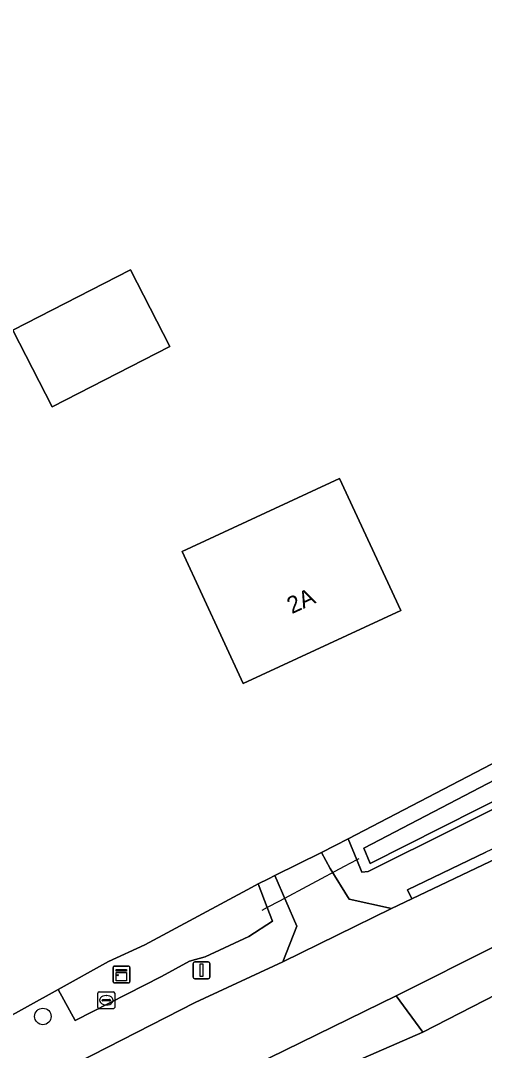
# Model space of a CAD drawing. Extents: x 164494 to 166241, y 382475 to 384495.
# Drawn here: x 165073.2 to 165100.7, y 383021.1 to 383082.2 of the extents above; entities that cross this region are included whole.
import ezdxf

# ---------------------------------------------------------------- set-up
doc = ezdxf.new("R2010")
doc.units = 0
for name, color, linetype in [('IMGEO_Berm_halfverhard', 7, 'Continuous'), ('IMGEO_Boom', 7, 'Continuous'), ('IMGEO_Duiker', 7, 'Continuous'), ('IMGEO_Erf', 7, 'Continuous'), ('IMGEO_Groenvoorziening', 7, 'Continuous'), ('IMGEO_Kast', 7, 'Continuous'), ('IMGEO_Lichtmast', 7, 'Continuous'), ('IMGEO_Oever', 7, 'Continuous'), ('IMGEO_Pand', 7, 'Continuous'), ('IMGEO_Pand_nummerreeks', 7, 'Continuous'), ('IMGEO_Rijbaan_lokaal_gesloten', 7, 'Continuous'), ('IMGEO_Rijbaan_lokaal_open', 7, 'Continuous'), ('IMGEO_Rioolput', 7, 'Continuous'), ('IMGEO_Waterloop', 7, 'Continuous')]:
    doc.layers.add(name, color=color, linetype=linetype)

msp = doc.modelspace()

# ---------------------------------------------------------------- linework, layer by layer
at = {"layer": 'IMGEO_Berm_halfverhard'}
msp.add_lwpolyline([(165124.917, 383044.186), (165114.926, 383039.545), (165106.055, 383035.28), (165100.825, 383032.871), (165096.175, 383030.648), (165096.433, 383030.107), (165101.084, 383032.33), (165106.315, 383034.739), (165115.179, 383039.001)], dxfattribs=at)
at = {"layer": 'IMGEO_Boom'}
msp.add_circle((165074.517, 383023.125), 0.489, dxfattribs=at)
at = {"layer": 'IMGEO_Duiker'}
msp.add_lwpolyline([(165093.282, 383032.484), (165093.164, 383032.421), (165092.411, 383032.019), (165088.575, 383029.973), (165087.842, 383029.582), (165087.517, 383029.409)], dxfattribs=at)
at = {"layer": 'IMGEO_Erf'}
for points in [[(165070.298, 383021.899), (165075.419, 383024.723), (165078.42, 383026.378), (165080.567, 383027.366), (165086.908, 383030.775), (165087.302, 383030.987), (165087.92, 383031.295), (165088.293, 383031.481), (165091.062, 383032.863), (165091.867, 383033.265), (165092.654, 383033.657), (165109.176, 383042.267), (165126.099, 383051.085), (165129.346, 383052.646), (165106.891, 383080.948), (165095.917, 383095.847), (165095.148, 383097.711), (165091.308, 383102.836), (165060.973, 383084.346)], [(165149.084, 382949.174), (165148.158, 382951.679), (165147.327, 382953.204), (165144.143, 382962.9), (165139.197, 382976.046), (165137.999, 382979.812), (165137.425, 382980.815), (165123.051, 383020.688), (165118.823, 383033.37), (165102.205, 383024.82), (165097.081, 383022.184), (165092.763, 383020.321), (165071.589, 383009.606), (165052.261, 382999.034), (165049.332, 382997.432), (165046.565, 382995.873), (165042.211, 382989.793), (165038.852, 382985.102), (165066.603, 382948.671), (165135.814, 382857.34)]]:
    msp.add_lwpolyline(points, dxfattribs=at)
for points in [[(165075.058, 383059.299), (165072.724, 383063.863), (165079.723, 383067.443), (165082.057, 383062.879)], [(165086.419, 383042.886), (165082.794, 383050.728), (165092.141, 383055.049), (165095.767, 383047.208)]]:
    msp.add_lwpolyline(points, close=True, dxfattribs=at)
at = {"layer": 'IMGEO_Groenvoorziening'}
msp.add_lwpolyline([(165130.436, 383049.949), (165093.844, 383031.73), (165093.464, 383031.692), (165093.164, 383032.421), (165092.654, 383033.657), (165091.867, 383033.265), (165091.062, 383032.863), (165091.582, 383031.909), (165092.716, 383030.076), (165095.219, 383029.526), (165096.433, 383030.107), (165096.175, 383030.648), (165100.825, 383032.871)], dxfattribs=at)
for points in [[(165088.775, 383026.373), (165089.6, 383028.476), (165088.293, 383031.481), (165087.92, 383031.295), (165087.302, 383030.987), (165087.842, 383029.582), (165088.149, 383028.783), (165086.745, 383027.872), (165084.158, 383026.667), (165083.217, 383026.412), (165081.553, 383025.502), (165076.433, 383022.884), (165075.419, 383024.723), (165070.298, 383021.899), (165072.217, 383018.147), (165083.565, 383023.951)], [(165088.149, 383028.783), (165087.842, 383029.582), (165087.302, 383030.987), (165086.908, 383030.775), (165080.567, 383027.366), (165078.42, 383026.378), (165075.419, 383024.723), (165076.433, 383022.884), (165081.553, 383025.502), (165083.217, 383026.412), (165084.158, 383026.667), (165086.745, 383027.872)], [(165092.763, 383020.321), (165097.081, 383022.184), (165095.49, 383024.344), (165083.246, 383018.36), (165078.697, 383016.073), (165072.324, 383012.931), (165050.894, 383001.427), (165052.261, 382999.034), (165071.589, 383009.606)]]:
    msp.add_lwpolyline(points, close=True, dxfattribs=at)
at = {"layer": 'IMGEO_Kast'}
for p, q in [((165078.681, 383025.188), (165078.681, 383026.029)), ((165078.681, 383026.029), (165078.681, 383025.188)), ((165078.756, 383026.113), (165079.597, 383026.113)), ((165079.597, 383026.113), (165078.756, 383026.113)), ((165079.681, 383026.038), (165079.681, 383025.197)), ((165079.681, 383025.197), (165079.681, 383026.038)), ((165079.606, 383025.113), (165078.765, 383025.113)), ((165078.765, 383025.113), (165079.606, 383025.113))]:
    msp.add_line(p, q, dxfattribs=at)
for points in [[(165078.876, 383025.903), (165079.476, 383025.903), (165079.476, 383025.818), (165078.876, 383025.818), (165078.876, 383025.903)], [(165078.876, 383025.728), (165079.476, 383025.728), (165079.476, 383025.239), (165078.876, 383025.239), (165078.876, 383025.728)]]:
    msp.add_lwpolyline(points, dxfattribs=at)
msp.add_circle((165078.96, 383025.577), 0.0377, dxfattribs=at)
for centre, start, end in [((165078.759, 383026.035), 92.4484, 184.28452), ((165078.759, 383026.035), 92.4484, 184.28452), ((165079.603, 383026.035), 2.4484, 94.28452), ((165079.603, 383026.035), 2.4484, 94.28452), ((165078.759, 383025.191), 182.4484, 274.28452), ((165078.759, 383025.191), 182.4484, 274.28452), ((165079.603, 383025.191), 272.4484, 4.28452), ((165079.603, 383025.191), 272.4484, 4.28452)]:
    msp.add_arc(centre, 0.0779, start, end, dxfattribs=at)
at = {"layer": 'IMGEO_Lichtmast'}
for p, q in [((165083.442, 383025.463), (165083.442, 383026.263)), ((165083.442, 383026.263), (165083.442, 383025.463)), ((165083.542, 383026.363), (165084.332, 383026.363)), ((165084.332, 383026.363), (165083.542, 383026.363)), ((165084.432, 383026.263), (165084.432, 383025.463)), ((165084.432, 383025.463), (165084.432, 383026.263)), ((165084.332, 383025.363), (165083.542, 383025.363)), ((165083.542, 383025.363), (165084.332, 383025.363))]:
    msp.add_line(p, q, dxfattribs=at)
msp.add_lwpolyline([(165083.862, 383026.238), (165084.012, 383026.238), (165084.012, 383025.488), (165083.862, 383025.488), (165083.862, 383026.238)], dxfattribs=at)
for centre, start, end in [((165083.542, 383026.263), 90, 180), ((165083.542, 383026.263), 90, 180), ((165084.332, 383026.263), 0, 90), ((165084.332, 383026.263), 360, 90), ((165083.542, 383025.463), 180, 270), ((165083.542, 383025.463), 180, 270), ((165084.332, 383025.463), 270, 0), ((165084.332, 383025.463), 270, 0)]:
    msp.add_arc(centre, 0.1, start, end, dxfattribs=at)
at = {"layer": 'IMGEO_Oever'}
for points in [[(165109.176, 383042.267), (165092.654, 383033.657), (165093.164, 383032.421), (165093.464, 383031.692), (165093.844, 383031.73), (165130.436, 383049.949)], [(165108.902, 383039.744), (165093.951, 383032.199), (165093.574, 383033.113), (165109.675, 383041.504)]]:
    msp.add_lwpolyline(points, dxfattribs=at)
at = {"layer": 'IMGEO_Pand'}
for points in [[(165082.057, 383062.879), (165079.723, 383067.443), (165072.724, 383063.863), (165075.058, 383059.299)], [(165086.419, 383042.886), (165095.767, 383047.208), (165092.141, 383055.049), (165082.794, 383050.728)]]:
    msp.add_lwpolyline(points, close=True, dxfattribs=at)
at = {"layer": 'IMGEO_Rijbaan_lokaal_gesloten'}
for points in [[(165125.134, 383043.627), (165115.179, 383039.001), (165106.315, 383034.739), (165101.084, 383032.33), (165096.433, 383030.107), (165095.219, 383029.526), (165088.775, 383026.373), (165083.565, 383023.951), (165072.217, 383018.147), (165071.399, 383017.729), (165067.244, 383015.604), (165062.647, 383013.041), (165061.822, 383012.581), (165054.231, 383008.739), (165048.937, 383005.869), (165048.666, 383005.698)], [(165050.894, 383001.427), (165072.324, 383012.931), (165078.697, 383016.073), (165083.246, 383018.36), (165095.49, 383024.344), (165101.496, 383027.356), (165108.474, 383031.009), (165123.201, 383037.752), (165131.209, 383041.458)]]:
    msp.add_lwpolyline(points, dxfattribs=at)
at = {"layer": 'IMGEO_Rijbaan_lokaal_open'}
for points in [[(165092.716, 383030.076), (165091.582, 383031.909), (165091.062, 383032.863), (165088.293, 383031.481), (165089.6, 383028.476), (165088.775, 383026.373), (165095.219, 383029.526)], [(165101.661, 383026.765), (165101.496, 383027.356), (165095.49, 383024.344), (165097.081, 383022.184), (165102.205, 383024.82)]]:
    msp.add_lwpolyline(points, close=True, dxfattribs=at)
at = {"layer": 'IMGEO_Rioolput'}
for p, q in [((165077.78, 383023.66), (165077.78, 383024.512)), ((165077.855, 383024.586), (165078.707, 383024.586)), ((165078.781, 383024.512), (165078.781, 383023.66)), ((165078.039, 383024.08), (165078.039, 383024.092)), ((165078.477, 383024.043), (165078.079, 383024.043)), ((165078.082, 383024.129), (165078.48, 383024.129)), ((165078.291, 383023.806), (165078.266, 383023.806)), ((165078.268, 383024.366), (165078.293, 383024.366)), ((165078.523, 383024.092), (165078.523, 383024.08)), ((165078.707, 383023.586), (165077.855, 383023.586))]:
    msp.add_line(p, q, dxfattribs=at)
for points in [[(165077.78, 383023.66), (165077.78, 383024.512)], [(165077.855, 383024.586), (165078.707, 383024.586)], [(165078.781, 383024.512), (165078.781, 383023.66)], [(165078.707, 383023.586), (165077.855, 383023.586)]]:
    msp.add_lwpolyline(points, dxfattribs=at)
for centre, radius, start, end in [((165077.857, 383024.51), 0.0765, 91.55205, 178.44795), ((165077.857, 383024.51), 0.0765, 91.55205, 178.44795), ((165078.705, 383024.51), 0.0765, 1.55205, 88.44795), ((165078.705, 383024.51), 0.0765, 1.55205, 88.44795), ((165078.079, 383024.089), 0.0403, 85.87752, 175.75265), ((165078.076, 383024.079), 0.0366, 178.93798, 274.71019), ((165078.48, 383024.086), 0.043, 264.86636, 352.45326), ((165078.484, 383024.091), 0.0386, 1.73085, 96.63898), ((165077.857, 383023.662), 0.0765, 181.55205, 268.44795), ((165077.857, 383023.662), 0.0765, 181.55205, 268.44795), ((165078.705, 383023.662), 0.0765, 271.55205, 358.44795), ((165078.705, 383023.662), 0.0765, 271.55205, 358.44795)]:
    msp.add_arc(centre, radius, start, end, dxfattribs=at)
for centre, major_axis, ratio, start_param, end_param in [((165078.267, 383024.086), (-0.387, 0.002), 0.722429, 4.712389, 7.853982), ((165078.292, 383024.086), (-0.39, 0.002), 0.717154, 1.570796, 4.712389)]:
    msp.add_ellipse(centre, major_axis=major_axis, ratio=ratio, start_param=start_param, end_param=end_param, dxfattribs=at)
at = {"layer": 'IMGEO_Waterloop'}
msp.add_lwpolyline([(165109.675, 383041.504), (165093.574, 383033.113), (165093.951, 383032.199), (165108.902, 383039.744)], dxfattribs=at)

# ---------------------------------------------------------------- texts
at = {"layer": 'IMGEO_Pand_nummerreeks'}
msp.add_text('2A', height=1, rotation=24.81322, dxfattribs=at).set_placement((165089.305, 383046.997))

doc.saveas('drawing.dxf')
